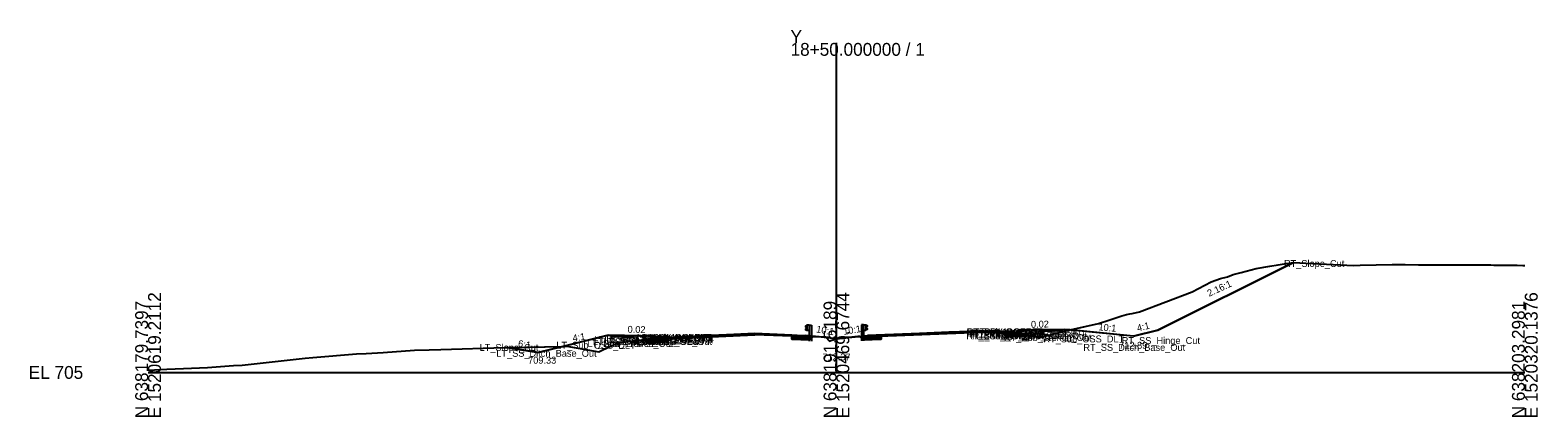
# Model space of a CAD drawing. Extents: x -26 to 303, y -10 to 5039.
# Drawn here: x -25.7 to 302.8, y 1990.3 to 2074.6 of the extents above; entities that cross this region are included whole.
import ezdxf

# ---------------------------------------------------------------- set-up
doc = ezdxf.new("R2010")
doc.units = 0
for name, color, linetype in [('Default', 7, 'Continuous'), ('Exist Cross Section Cell', 7, 'Continuous'), ('Exist XS Center Line Elevation Label', 7, 'Continuous'), ('Exist XS Ground Line', 7, 'Continuous'), ('Prop CMT Pvmt Course 1', 7, 'Continuous'), ('Prop CMT Pvmt Course 2', 7, 'Continuous'), ('Prop CMT Pvmt Course 3', 7, 'Continuous'), ('Prop CMT Pvmt Surface Shoulder', 7, 'Continuous'), ('Prop CMT Shld Paved Course 1', 7, 'Continuous'), ('Prop CMT Shld Paved Course 2', 7, 'Continuous'), ('Prop CMT Shld Paved Course 3', 7, 'Continuous'), ('Prop CMT Slope Grass', 7, 'Continuous'), ('Prop CMT Subgrade Earthwork', 7, 'Continuous'), ('Prop Conc 4in Sidewalk', 7, 'Continuous'), ('Prop XS Ditch Standard Text', 7, 'Continuous'), ('Prop XS Earthwork Shape', 7, 'Continuous'), ('Prop XS Side Slope Text', 7, 'Continuous'), ('Scratch_Level_0', 7, 'Continuous'), ('Typical Curb CELL', 7, 'Continuous'), ('Typical Guardrail CELL', 7, 'Continuous'), ('Typical Shoulder Slope Information CELL', 7, 'Continuous')]:
    doc.layers.add(name, color=color, linetype=linetype)

# ---------------------------------------------------------------- blocks, each defined once
blk = doc.blocks.new('2_6 CURB RIGHT')
at = {"layer": 'Typical Curb CELL'}
for p, q in [((0, -0.58), (0, 0)), ((0, 0), (1.75, -0.07)), ((2, 0.17), (2, 0.18)), ((2.5, 0.42), (2.24, 0.42)), ((2.31, 0.08), (2.33, -0.01)), ((2.46, 0.04), (2.31, 0.08)), ((2.33, -0.01), (2.46, 0.04)), ((2.5, -0.58), (2.5, 0.42)), ((2.5, -0.58), (0, -0.58)), ((0.26, -0.34), (0.35, -0.22)), ((0.38, -0.34), (0.26, -0.34)), ((0.35, -0.22), (0.38, -0.34)), ((1.03, -0.39), (1.09, -0.28)), ((1.19, -0.36), (1.03, -0.39)), ((1.09, -0.28), (1.19, -0.36)), ((1.51, -0.34), (1.6, -0.22)), ((1.63, -0.34), (1.51, -0.34)), ((1.6, -0.22), (1.63, -0.34)), ((2.27, -0.39), (2.34, -0.28)), ((2.44, -0.36), (2.27, -0.39)), ((2.34, -0.28), (2.44, -0.36))]:
    blk.add_line(p, q, dxfattribs=at)
for centre in [(2.27, 0.34), (2.43, 0.12), (2.49, 0.31), (0.01, -0.55), (0.02, -0.25), (0.03, -0.15), (0.07, -0.39), (0.09, -0.18), (0.17, -0.34), (0.2, -0.06), (0.22, -0.58), (0.3, -0.14), (0.34, -0.04), (0.38, -0.51), (0.49, -0.1), (0.52, -0.21), (0.59, -0.53), (0.67, -0.29), (0.69, -0.12), (0.7, -0.45), (0.71, -0.07), (0.76, -0.56), (0.79, -0.26), (0.93, -0.5), (0.97, -0.1), (1.09, -0.15), (1.11, -0.54), (1.26, -0.55), (1.27, -0.25), (1.28, -0.15), (1.32, -0.39), (1.34, -0.18), (1.42, -0.34), (1.45, -0.1), (1.47, -0.58), (1.54, -0.14), (1.63, -0.51), (1.74, -0.1), (1.77, -0.21), (1.84, -0.53), (1.92, -0.29), (1.94, -0.12), (1.95, -0.45), (1.96, -0.07), (2.01, -0.56), (2.04, -0.26), (2.18, -0.5), (2.22, -0.1), (2.34, -0.15), (2.35, -0.54)]:
    blk.add_circle(centre, 0.00802, dxfattribs=at)
for centre, start, end in [((1.76, 0.17), 267.6155, 0), ((2.24, 0.18), 90, 180)]:
    blk.add_arc(centre, 0.24, start, end, dxfattribs=at)

msp = doc.modelspace()

# ---------------------------------------------------------------- linework, layer by layer
at = {"layer": 'Exist Cross Section Cell'}
for p, q in [((150, 2000), (150, 2071.85)), ((0, 2000), (150, 2000)), ((150, 2000), (300, 2000))]:
    msp.add_line(p, q, dxfattribs=at)
at = {"layer": 'Exist XS Ground Line'}
msp.add_lwpolyline([(0, 2000.51), (4.11, 2000.68), (7.72, 2000.83), (12.94, 2001.11), (18.59, 2001.51), (20.47, 2001.61), (34.24, 2003.1), (35.91, 2003.28), (45.4, 2004.02), (47.49, 2004.1), (51.26, 2004.36), (58.04, 2004.82), (61.23, 2004.91), (63.81, 2005.02), (77.7, 2005.43), (78.47, 2005.46), (90.49, 2005.68), (91.27, 2005.69), (98.23, 2004.49), (100.62, 2005.62), (102.4, 2006.43), (108.71, 2007.23), (110.24, 2007.42), (110.58, 2007.43), (111.01, 2007.45), (112.1, 2007.5), (113.19, 2007.56), (113.85, 2007.61), (114.35, 2007.65), (115.09, 2007.68), (115.7, 2007.7), (117.36, 2007.79), (118.2, 2007.83), (118.93, 2007.86), (120.71, 2007.95), (122.78, 2008.06), (123.2, 2008.08), (125.81, 2008.22), (126.37, 2008.27), (128.21, 2008.26), (130.7, 2008.26), (132.85, 2008.24), (133.22, 2008.24), (135.17, 2008.23), (135.73, 2008.22), (136.24, 2008.22), (137.8, 2008.2), (138.49, 2008.18), (141.56, 2007.97), (144.57, 2007.83), (147.6, 2007.79), (148.46, 2006.81), (148.8, 2006.95), (150, 2007.37), (150.78, 2007.63), (151.99, 2007.69), (155.45, 2007.87), (159.73, 2008.11), (162.01, 2008.26), (163.33, 2008.31), (165.42, 2008.39), (165.85, 2008.41), (167.76, 2008.48), (168.36, 2008.51), (169.05, 2008.53), (170.86, 2008.61), (171.79, 2008.64), (173.6, 2008.72), (173.97, 2008.74), (174.85, 2008.75), (175.86, 2008.76), (177.03, 2008.79), (178.36, 2008.81), (179.92, 2008.84), (180.87, 2008.86), (182.65, 2008.88), (183.37, 2008.89), (183.85, 2008.9), (185.4, 2008.9), (185.77, 2008.87), (190.03, 2008.5), (190.75, 2008.44), (191.25, 2008.33), (194.31, 2007.58), (199.01, 2008.84), (207.11, 2010.64), (209.39, 2011.37), (212.19, 2012.37), (213.18, 2012.62), (213.92, 2012.8), (214.41, 2012.88), (216.02, 2013.18), (227.52, 2017.54), (231.67, 2019.73), (233.71, 2020.46), (235.2, 2020.88), (236.42, 2021.33), (238.22, 2021.81), (241.47, 2022.65), (244.42, 2023.19), (246.28, 2023.48), (248.03, 2023.75), (249.68, 2023.95), (252.25, 2023.8), (262.73, 2023.34), (264.11, 2023.41), (271.09, 2023.51), (273.93, 2023.51), (276.87, 2023.49), (285.08, 2023.48), (285.69, 2023.47), (286.19, 2023.47), (288.81, 2023.45), (290.87, 2023.44), (292.6, 2023.43), (293.28, 2023.42), (294.06, 2023.41), (295.79, 2023.4), (297.28, 2023.38), (298.3, 2023.37), (299.6, 2023.35), (300, 2023.34)], dxfattribs=at)
at = {"layer": 'Prop CMT Pvmt Course 1'}
for points in [[(113.25, 2007.59), (113.25, 2007.34)], [(113.25, 2007.34), (113.26, 2007.34)], [(113.26, 2007.34), (113.26, 2007.59)], [(140.25, 2007.91), (140.25, 2008.16)], [(159.75, 2007.91), (159.75, 2008.16)], [(186.74, 2008.57), (186.74, 2008.82)], [(186.75, 2008.57), (186.74, 2008.57)], [(186.75, 2008.82), (186.75, 2008.57)]]:
    msp.add_lwpolyline(points, dxfattribs=at)
at = {"layer": 'Prop CMT Pvmt Course 2'}
for points in [[(113.26, 2007.34), (113.25, 2007.34)], [(113.25, 2007.34), (113.25, 2007.09)], [(113.26, 2007.09), (113.26, 2007.34)], [(140.25, 2007.66), (140.25, 2007.91)], [(159.75, 2007.66), (159.75, 2007.91)], [(186.74, 2008.32), (186.74, 2008.57)], [(186.74, 2008.57), (186.75, 2008.57)], [(186.75, 2008.32), (186.74, 2008.32)], [(186.75, 2008.57), (186.75, 2008.32)], [(113.25, 2007.09), (113.26, 2007.09)]]:
    msp.add_lwpolyline(points, dxfattribs=at)
at = {"layer": 'Prop CMT Pvmt Course 3'}
for points in [[(140.25, 2007.28), (140.25, 2007.66)], [(159.75, 2007.28), (159.75, 2007.66)], [(186.74, 2008.32), (186.75, 2008.32)], [(186.74, 2007.95), (186.74, 2008.32)], [(186.75, 2007.95), (186.74, 2007.95)], [(186.75, 2008.32), (186.75, 2007.95)], [(113.26, 2007.09), (113.25, 2007.09)], [(113.25, 2007.09), (113.25, 2006.72)], [(113.25, 2006.72), (113.26, 2006.72)], [(113.26, 2006.72), (113.26, 2007.09)], [(140.26, 2007.28), (140.25, 2007.28)], [(159.74, 2007.28), (159.75, 2007.28)]]:
    msp.add_lwpolyline(points, dxfattribs=at)
at = {"layer": 'Prop CMT Pvmt Surface Shoulder'}
for points in [[(132.22, 2008.48), (112.25, 2007.54)], [(132.22, 2008.48), (143.25, 2008.04)], [(181.53, 2009.03), (156.75, 2008.04)], [(181.53, 2009.03), (187.75, 2008.78)]]:
    msp.add_lwpolyline(points, dxfattribs=at)
at = {"layer": 'Prop CMT Shld Paved Course 1'}
for p, q in [((143.51, 2007.78), (143.25, 2008.04)), ((156.49, 2007.78), (156.75, 2008.04)), ((181.54, 2008.78), (187.74, 2008.53))]:
    msp.add_line(p, q, dxfattribs=at)
for points in [[(112.25, 2007.3), (113.26, 2007.34)], [(113.25, 2007.34), (113.25, 2007.59)], [(113.26, 2007.34), (132.21, 2008.23)], [(140.25, 2007.91), (132.21, 2008.23)], [(159.4, 2007.89), (181.54, 2008.78)], [(187.75, 2008.53), (186.74, 2008.57)], [(186.75, 2008.57), (186.75, 2008.82)]]:
    msp.add_lwpolyline(points, dxfattribs=at)
at = {"layer": 'Prop CMT Shld Paved Course 2'}
for p, q in [((143.77, 2007.52), (143.51, 2007.78)), ((156.23, 2007.52), (156.49, 2007.78))]:
    msp.add_line(p, q, dxfattribs=at)
for points in [[(113.26, 2007.34), (112.25, 2007.3)], [(113.25, 2007.09), (113.25, 2007.34)], [(140.25, 2007.91), (143.51, 2007.78)], [(143.77, 2007.52), (140.25, 2007.66)], [(156.23, 2007.52), (159.75, 2007.66)], [(159.75, 2007.91), (156.49, 2007.78)], [(186.74, 2008.57), (187.75, 2008.53)], [(187.75, 2008.28), (186.74, 2008.32)], [(186.75, 2008.32), (186.75, 2008.57)], [(112.25, 2007.05), (113.26, 2007.09)]]:
    msp.add_lwpolyline(points, dxfattribs=at)
at = {"layer": 'Prop CMT Shld Paved Course 3'}
for p, q in [((144.16, 2007.13), (143.77, 2007.52)), ((155.84, 2007.13), (156.23, 2007.52)), ((190.25, 2008.2), (190.75, 2008.2)), ((190.75, 2008.2), (191.18, 2007.77)), ((109.25, 2006.97), (108.82, 2006.54)), ((109.75, 2006.97), (109.25, 2006.97))]:
    msp.add_line(p, q, dxfattribs=at)
for points in [[(140.25, 2007.66), (143.77, 2007.52)], [(159.75, 2007.66), (156.23, 2007.52)], [(186.74, 2008.32), (187.75, 2008.28)], [(191.18, 2007.77), (186.74, 2007.95)], [(186.75, 2007.95), (186.75, 2008.32)], [(108.82, 2006.54), (113.26, 2006.72)], [(113.26, 2007.09), (112.25, 2007.05)], [(113.25, 2006.72), (113.25, 2007.09)], [(144.16, 2007.13), (140.25, 2007.28)], [(155.84, 2007.13), (159.75, 2007.28)]]:
    msp.add_lwpolyline(points, dxfattribs=at)
at = {"layer": 'Prop CMT Slope Grass'}
for p, q in [((84.97, 2004.33), (100.25, 2008.15)), ((100.25, 2008.15), (109.75, 2007.96)), ((150, 2007.36), (143.25, 2008.04)), ((150, 2007.36), (156.75, 2008.04)), ((199.75, 2009.39), (190.25, 2009.2)), ((214.75, 2007.89), (199.75, 2009.39)), ((78.23, 2005.45), (84.97, 2004.33))]:
    msp.add_line(p, q, dxfattribs=at)
msp.add_lwpolyline([(214.75, 2007.89), (220.01, 2009.2), (249.45, 2023.92)], dxfattribs=at)
at = {"layer": 'Prop CMT Subgrade Earthwork'}
for p, q in [((108.82, 2006.54), (107.35, 2008.02)), ((113.26, 2006.72), (113.26, 2007.59)), ((140.25, 2008.16), (140.25, 2007.28)), ((159.75, 2008.16), (159.75, 2007.28)), ((186.74, 2007.95), (186.74, 2008.82)), ((187.75, 2008.78), (187.75, 2008.2)), ((187.75, 2008.2), (190.25, 2008.2)), ((190.25, 2008.2), (190.25, 2009.2)), ((191.18, 2007.77), (192.65, 2009.25))]:
    msp.add_line(p, q, dxfattribs=at)
for points in [[(140.25, 2008.16), (140.25, 2007.28), (140.26, 2007.28)], [(144.16, 2007.13), (144.91, 2007.87)], [(155.84, 2007.13), (155.09, 2007.87)], [(159.75, 2008.16), (159.75, 2007.28), (159.74, 2007.28)], [(186.74, 2007.95), (191.18, 2007.77)], [(113.26, 2006.72), (108.82, 2006.54)], [(140.25, 2007.28), (144.16, 2007.13)], [(159.75, 2007.28), (155.84, 2007.13)]]:
    msp.add_lwpolyline(points, dxfattribs=at)
at = {"layer": 'Prop Conc 4in Sidewalk'}
for p, q in [((100.75, 2008.14), (100.75, 2007.81)), ((100.75, 2007.81), (105.75, 2007.71)), ((105.75, 2008.04), (105.75, 2007.71)), ((194.25, 2009.28), (194.25, 2008.94)), ((199.25, 2009.04), (194.25, 2008.94)), ((199.25, 2009.38), (199.25, 2009.04))]:
    msp.add_line(p, q, dxfattribs=at)
at = {"layer": 'Prop XS Earthwork Shape'}
for points in [[(235.2, 2020.88), (236.42, 2021.33), (238.22, 2021.81), (241.47, 2022.65), (244.42, 2023.19), (246.28, 2023.48), (248.03, 2023.75), (249.45, 2023.92), (220.01, 2009.2), (214.75, 2007.89), (200.94, 2009.27), (207.11, 2010.64), (209.39, 2011.37), (212.19, 2012.37), (213.18, 2012.62), (213.92, 2012.8), (214.41, 2012.88), (216.02, 2013.18), (227.52, 2017.54), (231.67, 2019.73), (233.71, 2020.46)], [(108.2, 2007.16), (107.35, 2008.01), (100.25, 2008.15), (90.35, 2005.68), (90.49, 2005.68), (91.27, 2005.69), (98.23, 2004.49), (100.62, 2005.62), (102.4, 2006.43)], [(108.82, 2006.54), (108.2, 2007.16), (108.71, 2007.23), (110.24, 2007.42), (110.58, 2007.43), (111.01, 2007.45), (112.1, 2007.5), (113.19, 2007.56), (113.26, 2007.57), (113.26, 2006.72)], [(113.99, 2007.63), (113.26, 2007.59), (113.26, 2007.57), (113.85, 2007.61)], [(113.99, 2007.63), (114.35, 2007.65), (115.09, 2007.68), (115.62, 2007.7)], [(115.62, 2007.7), (115.7, 2007.7), (116.26, 2007.73)], [(126.37, 2008.27), (127.62, 2008.26), (116.26, 2007.73), (117.36, 2007.79), (118.2, 2007.83), (118.93, 2007.86), (120.71, 2007.95), (122.78, 2008.06), (123.2, 2008.08), (125.81, 2008.22)], [(135.17, 2008.23), (135.73, 2008.22), (136.24, 2008.22), (137.8, 2008.2), (138.49, 2008.18), (140.25, 2008.06), (140.25, 2008.16), (132.22, 2008.48), (127.62, 2008.26), (128.21, 2008.26), (130.7, 2008.26), (132.85, 2008.24), (133.22, 2008.24)], [(144.57, 2007.83), (144.86, 2007.83), (144.16, 2007.13), (140.26, 2007.28), (140.25, 2008.06), (141.56, 2007.97)], [(144.86, 2007.83), (144.91, 2007.87), (145.44, 2007.82)], [(147.6, 2007.79), (147.78, 2007.58), (145.44, 2007.82)], [(147.78, 2007.58), (148.46, 2006.81), (148.8, 2006.95), (150, 2007.36)], [(150.78, 2007.63), (151.99, 2007.69), (154.66, 2007.83), (150, 2007.36)], [(154.66, 2007.83), (155.11, 2007.85), (155.09, 2007.87)], [(155.84, 2007.13), (155.11, 2007.85), (155.45, 2007.87), (159.73, 2008.11), (159.75, 2008.11), (159.74, 2007.28)], [(159.75, 2008.16), (159.75, 2008.11), (161.62, 2008.23)], [(165.85, 2008.41), (167.76, 2008.48), (168.36, 2008.51), (169.05, 2008.53), (170.86, 2008.61), (171.79, 2008.64), (173.6, 2008.72), (173.97, 2008.74), (174.46, 2008.75), (161.62, 2008.23), (162.01, 2008.26), (163.33, 2008.31), (165.42, 2008.39)], [(181.53, 2009.03), (174.46, 2008.75), (174.85, 2008.75), (175.86, 2008.76), (177.03, 2008.79), (178.36, 2008.81), (179.92, 2008.84), (180.87, 2008.86), (182.65, 2008.88), (183.37, 2008.89), (183.85, 2008.9), (184.75, 2008.9)], [(184.75, 2008.9), (185.4, 2008.9), (185.77, 2008.87), (186, 2008.85)], [(186.74, 2008.79), (186.74, 2008.82), (186, 2008.85)], [(187.75, 2008.7), (187.75, 2008.2), (190.25, 2008.2), (190.25, 2008.48), (190.75, 2008.44), (191.25, 2008.33), (191.64, 2008.23), (191.18, 2007.77), (186.74, 2007.95), (186.74, 2008.79)], [(187.75, 2008.7), (187.75, 2008.2), (190.25, 2008.2), (190.25, 2008.48), (190.03, 2008.5)], [(199.01, 2008.84), (200.94, 2009.27), (199.75, 2009.39), (192.65, 2009.25), (191.64, 2008.23), (194.31, 2007.58)], [(78.23, 2005.45), (78.47, 2005.46), (90.35, 2005.68), (84.97, 2004.33)]]:
    msp.add_lwpolyline(points, close=True, dxfattribs=at)
at = {"layer": 'Typical Guardrail CELL'}
for p, q in [((143.57, 2010.32), (143.28, 2010.11)), ((143.57, 2009.78), (143.28, 2009.99)), ((143.57, 2009.69), (143.28, 2009.49)), ((143.57, 2009.16), (143.28, 2009.36)), ((144.07, 2010.32), (143.57, 2010.32)), ((143.57, 2010.32), (143.57, 2009.16)), ((143.57, 2009.74), (143.57, 2009.78)), ((143.57, 2009.74), (143.57, 2009.69)), ((144.07, 2009.16), (143.57, 2009.16)), ((144.07, 2010.32), (144.07, 2007.83)), ((144.07, 2010.32), (144.57, 2010.32)), ((144.07, 2007.83), (144.57, 2007.83)), ((144.07, 2007.83), (144.07, 2006.82)), ((144.57, 2010.32), (144.57, 2007.83)), ((144.57, 2007.83), (144.57, 2006.82)), ((155.93, 2010.36), (155.43, 2010.36)), ((155.43, 2010.36), (155.43, 2007.87)), ((155.93, 2007.87), (155.43, 2007.87)), ((155.43, 2007.87), (155.43, 2006.86)), ((155.93, 2010.36), (155.93, 2007.87)), ((155.93, 2010.36), (156.43, 2010.36)), ((155.93, 2009.2), (156.43, 2009.2)), ((155.93, 2007.87), (155.93, 2006.86)), ((156.43, 2010.36), (156.43, 2009.2)), ((156.43, 2010.36), (156.72, 2010.15)), ((156.43, 2009.82), (156.72, 2010.02)), ((156.43, 2009.78), (156.43, 2009.82)), ((156.43, 2009.78), (156.43, 2009.73)), ((156.43, 2009.73), (156.72, 2009.53)), ((156.43, 2009.2), (156.72, 2009.4))]:
    msp.add_line(p, q, dxfattribs=at)
for centre, start, end in [((143.33, 2010.05), 125.003, 235.0112), ((143.33, 2009.42), 125.0059, 235.0366), ((156.67, 2010.09), 304.9888, 54.997), ((156.67, 2009.46), 304.9634, 54.9941)]:
    msp.add_arc(centre, 0.0776, start, end, dxfattribs=at)

# ---------------------------------------------------------------- block references
at = {"layer": 'Prop CMT Slope Grass', "yscale": -1, "rotation": 180}
msp.add_blockref('2_6 CURB RIGHT', (112.25, 2007.54), dxfattribs=at)
at = {"layer": 'Prop CMT Slope Grass'}
msp.add_blockref('2_6 CURB RIGHT', (187.75, 2008.78), dxfattribs=at)

# ---------------------------------------------------------------- texts
at = {"layer": 'Default'}
msp.add_text('-', height=0.0001, dxfattribs=at).set_placement((0, 2000))
at = {"layer": 'Exist Cross Section Cell'}
for s, p in [('Y', (140, 2071.85)), ('18+50.000000 / 1', (140, 2069.05)), ('EL 705', (-26, 1998.6))]:
    msp.add_text(s, height=2.8, dxfattribs=at).set_placement(p)
for s, p in [('E 1520619.2112', (2.8, 1990)), ('E 1520469.6744', (152.8, 1990)), ('E 1520320.1376', (302.8, 1990)), ('N 638179.7397', (0, 1990)), ('N 638191.5189', (150, 1990)), ('N 638203.2981', (300, 1990))]:
    msp.add_text(s, height=2.8, rotation=90, dxfattribs=at).set_placement(p)
at = {"layer": 'Exist XS Center Line Elevation Label'}
msp.add_text('712.37', height=1.5, dxfattribs=at).set_placement((146.95, 2002.62))
at = {"layer": 'Prop XS Ditch Standard Text'}
for s, p in [('712.89', (211.6, 2005.17)), ('709.33', (82.81, 2001.91))]:
    msp.add_text(s, height=1.5, dxfattribs=at).set_placement(p)
at = {"layer": 'Prop XS Side Slope Text'}
for s, rotation, p in [('2.16:1', 24.8022, (231.22, 2016.48)), ('10:1', 354.8852, (207.04, 2009.2)), ('4:1', 14.0362, (215.67, 2008.89)), ('4:1', 9.4623, (92.63, 2006.72)), ('10:1', 350.5377, (145.51, 2008.74)), ('10:1', 9.4623, (151.61, 2008.19)), ('6:1', 350.5191, (80.53, 2005.62))]:
    msp.add_text(s, height=1.5, rotation=rotation, dxfattribs=at).set_placement(p)
at = {"layer": 'Scratch_Level_0'}
for s, p in [('RT_Slope_Cut', (247.52, 2023)), ('LT_PS3_Shelf_Out', (96.95, 2005.95)), ('LT_GS_OS_CTL', (97.19, 2006.41)), ('LT_PS3_OEOP', (99.15, 2005.98)), ('LT_PS2_OEOP', (99.41, 2006.24)), ('LT_PS1_OEOP', (99.85, 2006.5)), ('LT_PV2_PGL_Out', (106.36, 2006.63)), ('LT_PV3_PGL_Out', (106.36, 2006.38)), ('LT_Sub_PGL_Out', (106.4, 2006)), ('LT_Sub_Out_DLT', (106.49, 2006.88)), ('LT_PV1_PGL_Out', (106.54, 2006.88)), ('LT_PV2_OEOT', (107.61, 2006.63)), ('LT_PV3_OEOT', (107.61, 2006.38)), ('LT_Sub_OEOT', (107.64, 2006)), ('LT_PV1_OEOT', (107.79, 2006.88)), ('RT_PV2_PGL_Out', (178.27, 2007.85)), ('RT_PV3_PGL_Out', (178.27, 2007.6)), ('RT_Sub_PGL_Out', (178.31, 2007.23)), ('RT_Sub_Out_DLT', (178.37, 2008.1)), ('RT_PV1_PGL_Out', (178.45, 2008.1)), ('RT_PV2_OEOT', (179.54, 2007.85)), ('RT_PV3_OEOT', (179.54, 2007.6)), ('RT_Sub_OEOT', (179.57, 2007.23)), ('RT_PV1_OEOT', (179.72, 2008.1)), ('RT_Sub_Trench_Out', (186.5, 2006.85)), ('RT_PS3_Shelf_Out', (186.93, 2007.24)), ('RT_PS1_OEOP', (187.78, 2007.78)), ('RT_PS2_OEOP', (187.86, 2007.52)), ('RT_PS3_OEOP', (188.12, 2007.26)), ('RT_GS_OS_CTL', (189.12, 2007.7)), ('RT_Sub_OSS_DLT', (195.1, 2006.55)), ('RT_SS_Hinge_Cut', (212.16, 2006.2)), ('LT_Slope_Cut', (72.24, 2004.7)), ('LT_SS_Ditch_Base_Out', (75.88, 2003.41)), ('LT_Sub_OSS_DLT', (88.96, 2005.19)), ('LT_Sub_Trench_Out', (95.74, 2005.56)), ('RT_SS_Ditch_Base_Out', (203.81, 2004.7))]:
    msp.add_text(s, height=1.5, dxfattribs=at).set_placement(p)
at = {"layer": 'Typical Shoulder Slope Information CELL'}
for rotation, p in [(1.1403, (192.4, 2009.73)), (358.8597, (104.48, 2008.66))]:
    msp.add_text('0.02', height=1.5, rotation=rotation, dxfattribs=at).set_placement(p)

doc.saveas('drawing.dxf')
